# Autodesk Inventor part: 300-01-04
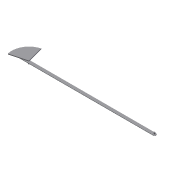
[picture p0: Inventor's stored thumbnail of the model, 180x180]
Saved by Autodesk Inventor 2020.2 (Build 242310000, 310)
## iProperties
Created: 2014-10
Part Number: 300-01-04
Material: Ogólny
Document SubType Name: Modeling
Designer: F.Stasiak
Density: 1 g/cm^3
Appearance: Domyślna
Catalog Web Link: www.expertbooks.pl
Manager: www.cadconsulting.pl
Company: Fabian Stasiak CAD Consulting
Author: F.Stasiak
Subject: Zbiór ćwiczeń. Autodesk Inventor 2020. Kurs Professional
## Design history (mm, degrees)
sketch "Szkic1"
  geometry: L1 (0, 0)-(800, 0); L2 (0, -10)-(800, -10); L3 (800, 10)-(0, 10); A1 r 10 centre (0, 0) between (0, 10) and (0, -10); A2 r 10 centre (800, 0) between (800, -10) and (800, 10); 1 further point
  constraints: 8 end point, 4 point on circle, 4 tangent, 2 centre point, 1 horizontal, 1 midpoint, 1 parallel
  dimensions: "d0" = 800 distance of L1.start L1.end; "d1" = 20 diameter of A2
extrude "Wyciągnięcie proste1" new body sketch "Szkic1" stored distance "d2" = 3; taper "d3" = 0 deg
sketch "Szkic2"
  geometry: C1 r 4 at (800, 0); A1 r 10 centre (800, 0) between (800, -10) and (800, 10) reference; 1 further point
  constraints: 1 centre point, 1 coincident
  dimensions: "d4" = 8 diameter of C1
extrude "Wyciągnięcie proste2" join sketch "Szkic2" distance "d5" = 10; taper "d6" = 0 deg
sketch "Szkic3"
  geometry: C1 r 4 at (0, 0); 1 further point
  constraints: 1 centre point, 1 coincident
  dimensions: "d7" = 8 diameter of C1
extrude "Wyciągnięcie proste3" join sketch "Szkic3" distance "d8" = 10; taper "d9" = 0 deg
sketch "Szkic4"
  geometry: L1 (0, -10)-(800, -10) reference; L2 (800, 10)-(0, 10) reference; L3 (0, -10)-(-100, -10); L4 (-100, 10)-(0, 10); A1 r 10 centre (-100, 0) between (-100, 10) and (-100, -10); A2 r 10 centre (0, 0) between (0, 10) and (0, -10) reference; 1 further point
  constraints: 4 end point, 2 point on circle, 2 tangent, 1 centre point, 1 equal radius, 1 horizontal, 1 parallel
  dimensions: "d10" = 100 distance of L4.start L2.end
extrude "Wyciągnięcie proste4" join sketch "Szkic4" distance "d11" = 3; taper "d12" = 0 deg
sketch "Szkic5"
  geometry: L1 (0, 0)-(-28.47, 106.252); L2 (0, 0)-(-106.252, -28.47); L3 (800, -10)-(-100, -10) reference; A1 r 110 centre (0, 0) between (-28.47, 106.252) and (-106.252, -28.47); 1 further point
  constraints: 4 end point, 2 point on circle, 1 centre point, 1 coincident, 1 perpendicular
  dimensions: "d13" = 220 diameter of A1; "d14" = 15 deg angle of L2 L3
extrude "Wyciągnięcie proste5" join sketch "Szkic5" distance "d15" = 5; taper "d16" = 0 deg
node "Bryła1"
